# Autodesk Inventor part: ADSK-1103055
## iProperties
Created: 2000-08
Part Number: ADSK-1103055
Material: Aluminum-6061
Document SubType Name: Modeling
Mass: 8.22663 g
Surface Area: 26.2406 cm^2
Volume: 3.03566 cm^3
Density: 2.71 g/cm^3
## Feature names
1. Derived Body1 [Tagging]
